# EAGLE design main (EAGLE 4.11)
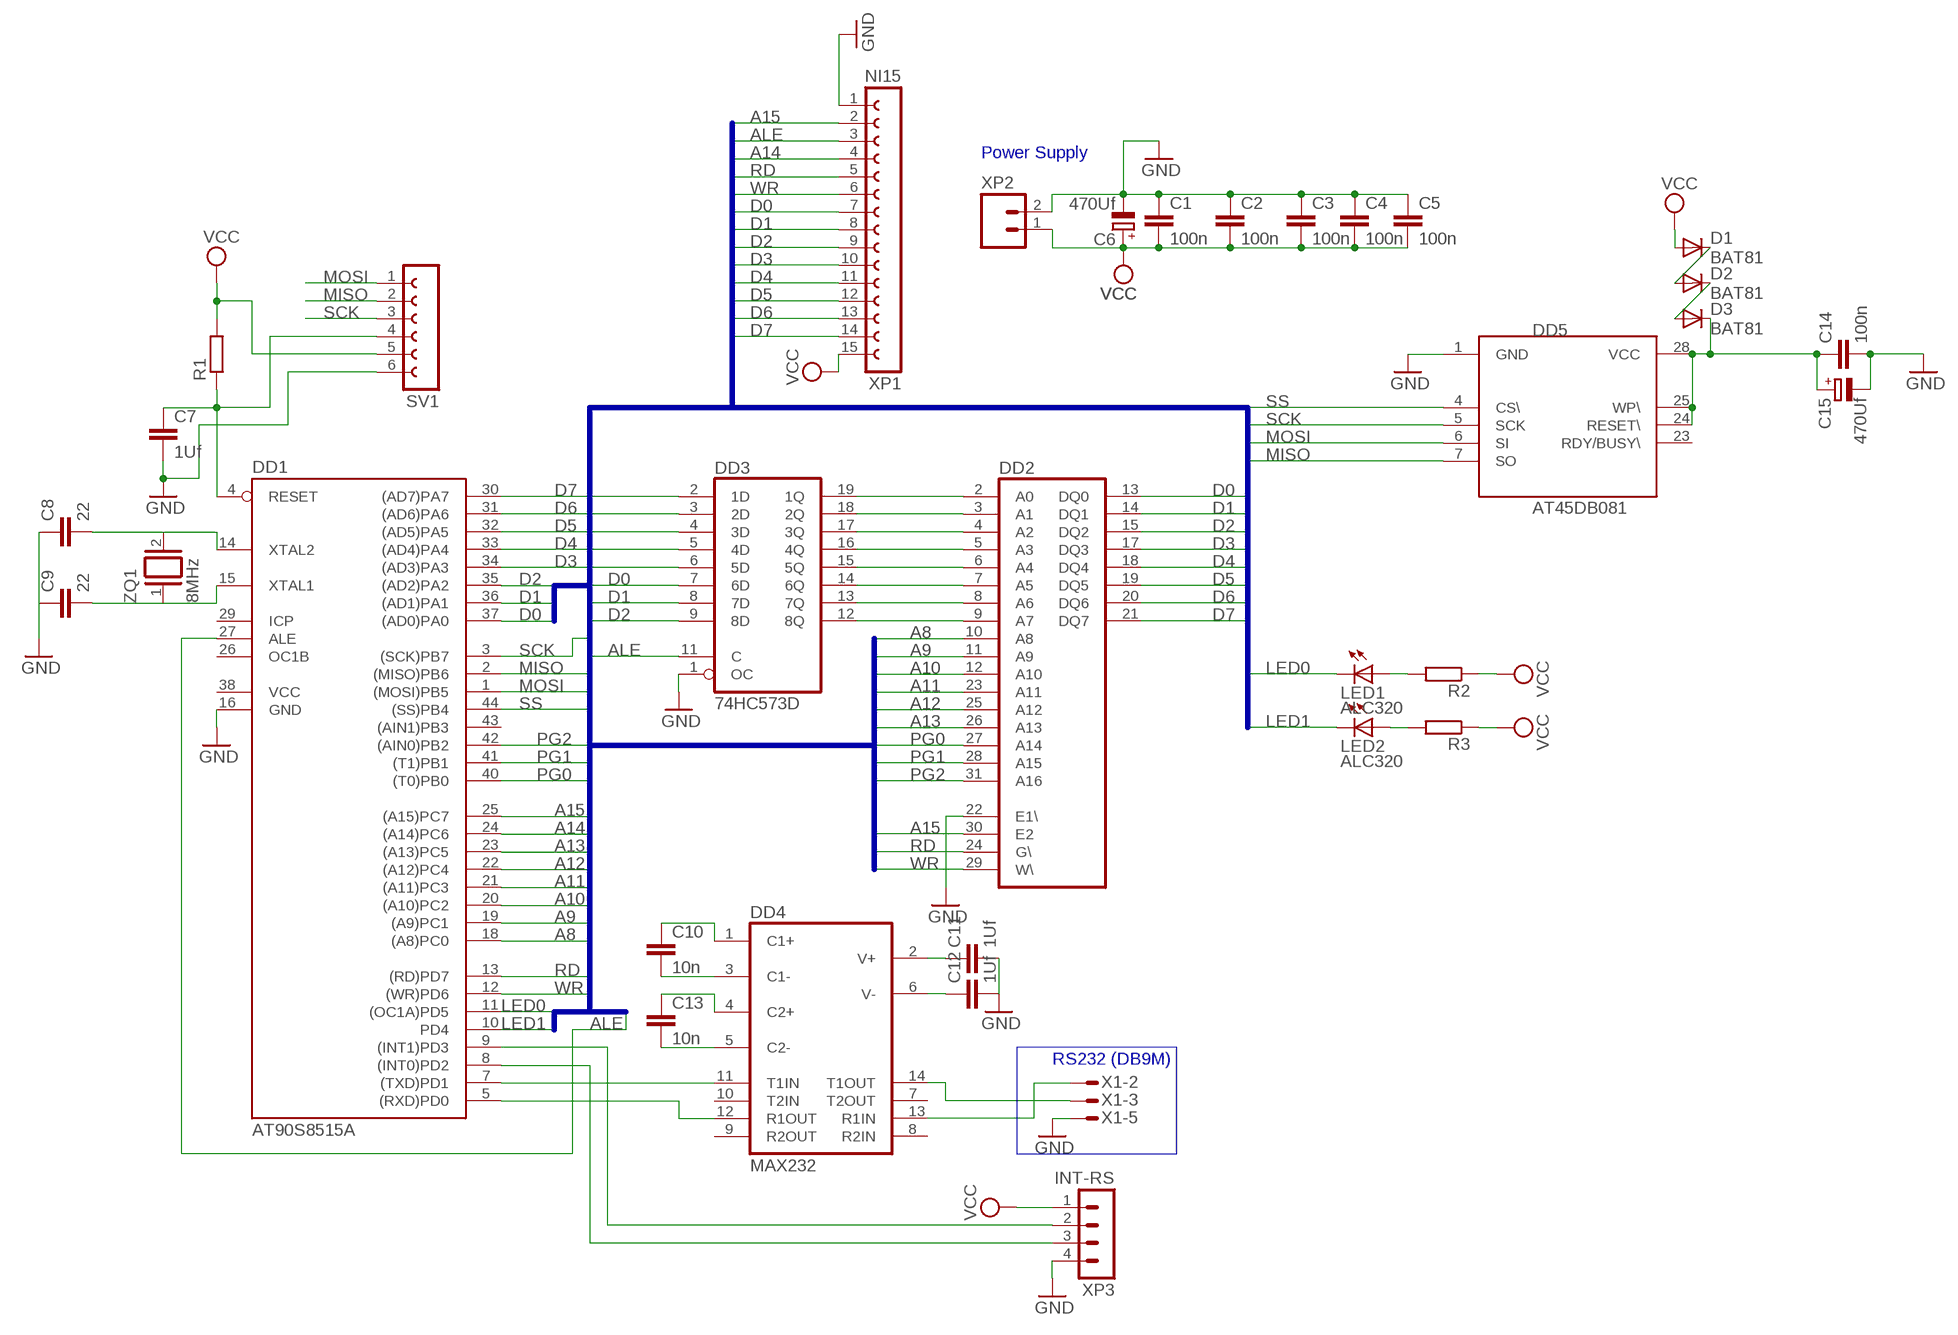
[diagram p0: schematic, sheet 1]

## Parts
C1  100n  C-EUC0805K  [C0805K]
C2  100n  C-EUC0805K  [C0805K]
C3  100n  C-EUC0805K  [C0805K]
C4  100n  C-EUC0805K  [C0805K]
C5  100n  C-EUC0805K  [C0805K]
C6  470Uf  CPOL-EUE2.5-6  [E2,5-6]
C7  1Uf  C-EUC0805K  [C0805K]
C8  22  C-EUC0805K  [C0805K]
C9  22  C-EUC0805K  [C0805K]
C10  10n  C-EUC0805K  [C0805K]
C11  1Uf  C-EUC0805K  [C0805K]
C12  1Uf  C-EUC0805K  [C0805K]
C13  10n  C-EUC0805K  [C0805K]
C14  100n  C-EUC0805K  [C0805K]
C15  470Uf  CPOL-EUE2.5-6  [E2,5-6]
D1  BAT81  [DO34-7]
D2  BAT81  [DO34-7]
D3  BAT81  [DO34-7]
DD1  AT90S8515A  [TQFP44]
DD2  MCM6226A  [SOJ32/4]
DD3  74HC573D  [SO20W]
DD4  MAX232  [DIL16]
DD5  AT45DB081  [AT45DB081-SOIC28]
LED1  ALC320  LED3MM  [LED3MM]
LED2  ALC320  LED3MM  [LED3MM]
R1  R-EU_R0805  [R0805]
R2  R-EU_R0805  [R0805]
R3  R-EU_R0805  [R0805]
SV1  FE06-1  [FE06]
X1  M09HPS  [M09HP]
XP1  NI15  FE15-1  [FE15]
XP2  M02  [02P]
XP3  INT-RS  MA04-1  [MA04-1]
ZQ1  8MHz  XTAL/S  [QS]

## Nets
A8: DD1.18((A8)PC0) DD2.10(A8)
A9: DD1.19((A9)PC1) DD2.11(A9)
A10: DD1.20((A10)PC2) DD2.12(A10)
A11: DD1.21((A11)PC3) DD2.23(A11)
A12: DD1.22((A12)PC4) DD2.25(A12)
A13: DD1.23((A13)PC5) DD2.26(A13)
A14: DD1.24((A14)PC6) XP1.4
A15: DD1.25((A15)PC7) DD2.30(E2) XP1.2
ALE: DD1.27(ALE) DD3.11(C) XP1.3
D0: DD1.37((AD0)PA0) DD2.13(DQ0) DD3.7(6D) XP1.7
D1: DD1.36((AD1)PA1) DD2.14(DQ1) DD3.8(7D) XP1.8
D2: DD1.35((AD2)PA2) DD2.15(DQ2) DD3.9(8D) XP1.9
D3: DD1.34((AD3)PA3) DD2.17(DQ3) DD3.6(5D) XP1.10
D4: DD1.33((AD4)PA4) DD2.18(DQ4) DD3.5(4D) XP1.11
D5: DD1.32((AD5)PA5) DD2.19(DQ5) DD3.4(3D) XP1.12
D6: DD1.31((AD6)PA6) DD2.20(DQ6) DD3.3(2D) XP1.13
D7: DD1.30((AD7)PA7) DD2.21(DQ7) DD3.2(1D) XP1.14
GND: C1.1 C2.1 C3.1 C4.1 C5.1 C6.- C7.2 C8.1 C9.1 C11.2 C12.2 C14.2 C15.- DD1.16(GND) DD2.22(E1\) DD3.1(OC) DD5.1(GND) SV1.6 X1.5 XP1.1 XP2.2 XP3.4
LED0: DD1.11((OC1A)PD5) LED1.K(C)
LED1: DD1.10(PD4) LED2.K(C)
MISO: DD1.2((MISO)PB6) DD5.7(SO) SV1.2
MOSI: DD1.1((MOSI)PB5) DD5.6(SI) SV1.1
N$1: C8.2 DD1.14(XTAL2) ZQ1.2
N$2: C9.2 DD1.15(XTAL1) ZQ1.1
N$3: DD2.2(A0) DD3.19(1Q)
N$4: DD2.3(A1) DD3.18(2Q)
N$5: DD2.4(A2) DD3.17(3Q)
N$6: DD2.5(A3) DD3.16(4Q)
N$7: DD2.6(A4) DD3.15(5Q)
N$8: DD2.7(A5) DD3.14(6Q)
N$9: DD2.8(A6) DD3.13(7Q)
N$10: DD2.9(A7) DD3.12(8Q)
N$11: DD1.8((INT0)PD2) XP3.3
N$12: C7.1 DD1.4(RESET) R1.1 SV1.4
N$13: C12.1 DD4.6(V-)
N$14: C11.1 DD4.2(V+)
N$15: C10.1 DD4.1(C1+)
N$16: C10.2 DD4.3(C1-)
N$17: C13.2 DD4.5(C2-)
N$18: C13.1 DD4.4(C2+)
N$19: DD1.7((TXD)PD1) DD4.11(T1IN)
N$20: DD1.5((RXD)PD0) DD4.12(R1OUT)
N$21: DD4.14(T1OUT) X1.3
N$22: DD4.13(R1IN) X1.2
N$23: DD1.9((INT1)PD3) XP3.2
N$24: LED2.A R3.2
N$25: LED1.A R2.2
N$26: C14.1 C15.+ D3.C DD5.24(RESET\) DD5.25(WP\) DD5.28(VCC)
N$27: D1.C D2.A
N$28: D2.C D3.A
PG0: DD1.40((T0)PB0) DD2.27(A14)
PG1: DD1.41((T1)PB1) DD2.28(A15)
PG2: DD1.42((AIN0)PB2) DD2.31(A16)
RD: DD1.13((RD)PD7) DD2.24(G\) XP1.5
SCK: DD1.3((SCK)PB7) DD5.5(SCK) SV1.3
SS: DD1.44((SS)PB4) DD5.4(CS\)
VCC: C1.2 C2.2 C3.2 C4.2 C5.2 C6.+ D1.A R1.2 R2.1 R3.1 SV1.5 XP1.15 XP2.1 XP3.1
WR: DD1.12((WR)PD6) DD2.29(W\) XP1.6
Unconnected: DD1.6(NC1) DD1.17(NC2) DD1.26(OC1B) DD1.28(NC3) DD1.29(ICP) DD1.39(NC4) DD1.43((AIN1)PB3) DD4.7(T2OUT) DD4.8(R2IN) DD4.9(R2OUT) DD4.10(T2IN) DD5.23(RDY/BUSY\) X1.1 X1.4 X1.6 X1.7 X1.8 X1.9

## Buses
B$1
B$2

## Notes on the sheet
- Power Supply
- RS232 (DB9M)

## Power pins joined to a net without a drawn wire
GND: DD2.16(GND) DD3.10(GND) DD4.15(GND)
VCC: DD1.38(VCC) DD2.32(VCC) DD3.20(VCC) DD4.16(VCC)

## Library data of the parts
C1-C5 C7-C14 = rcl:C-EU: CAPACITOR, European symbol
C6 C15 = rcl:CPOL-EU: POLARIZED CAPACITOR, European symbol
D1-D3 = diode:BAT81: DIODE
DD1 = atmel:AT90S8515: MICROCONTROLLER 8 Kbytes FLASH 512 bytes SRAM 512 bytes EEPROM UART
DD2 = memory-sram:MCM6226A: MEMORY
DD3 = 74xx-eu:74*573: 8-bit D latch BUS DRIVER
DD4 = maxim:MAX232: RS232 TRANSEIVER
DD5 = flash:AT45DB081: Package: SOIC32, 32-pin SOIC package, 1,27mm between center of pins
LED1 LED2 = led:LED: LED
R1-R3 = rcl:R-EU_: RESISTOR, European symbol
SV1 = con-lsta:FE06-1: FEMALE HEADER
X1 = con-subd:M09?S: SUB-D
XP1 = con-lsta:FE15-1: FEMALE HEADER
XP2 = con-amp-quick:M02: AMP QUICK CONNECTOR
XP3 = con-lstb:MA04-1: PIN HEADER
ZQ1 = special:XTAL/S: CRYSTAL

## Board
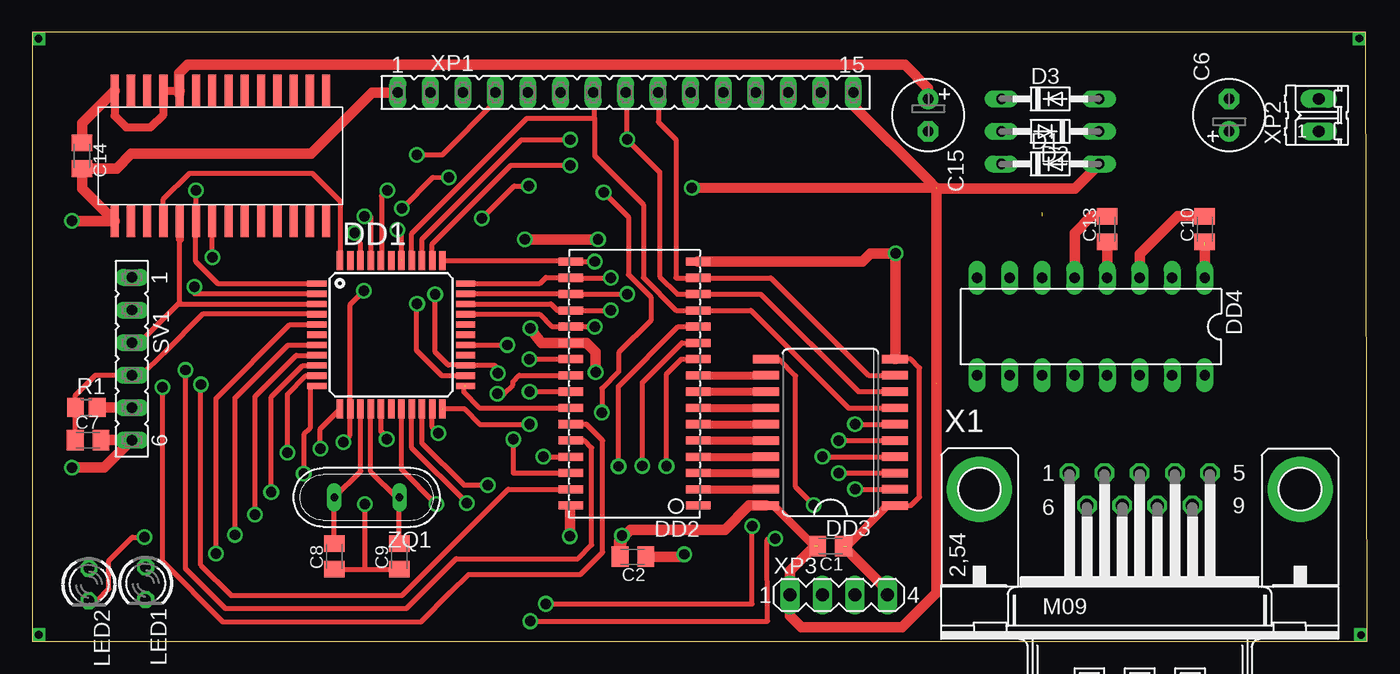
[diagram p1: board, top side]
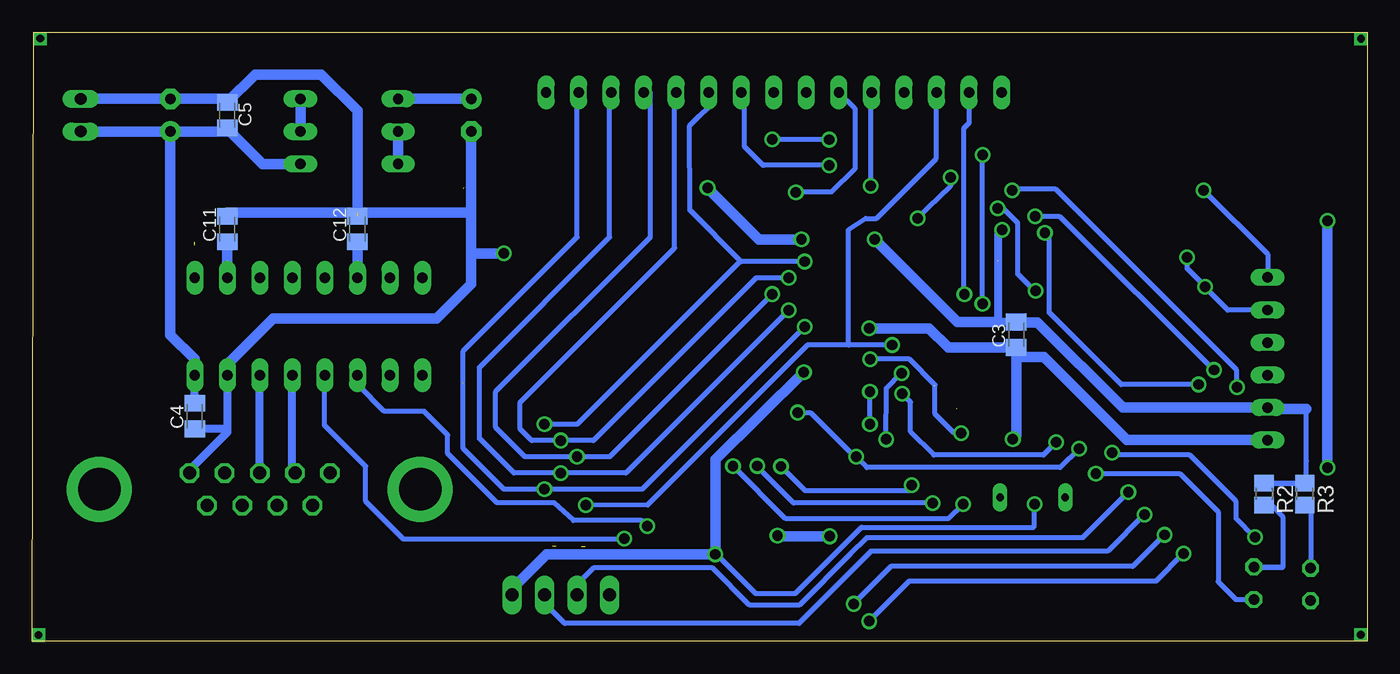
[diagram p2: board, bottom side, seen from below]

Size 104.21 x 47.58 mm. Coordinates in mm from the lower left corner, seen from the top.
Outline: 0,0 104.21,0 104.11,47.58 0,47.58 0,0
Copper layers (1*16): Top 0.035mm / dielectric 1.5mm / Bottom 0.035mm
Design rules "default": minimum track width 10mil, minimum drill 24mil, track to track 8mil, track to pad 8mil, pad to pad 8mil, via to via 8mil, smd to smd 8mil, copper to edge 40mil, drill to drill 8mil, minimum pad ring 10mil, minimum via ring 8mil, stop-mask expansion 4mil, vias tented up to drill 0mil, thermal gap 10mil

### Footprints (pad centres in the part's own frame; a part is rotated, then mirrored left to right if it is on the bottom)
C0805K = smd 1.3 x 1.6: 1 -1,0; 2 1,0
E2,5-6 = drill 0.813 pad 1.6 round: + -1.27,0 | drill 0.813 pad 1.6 octagon: - 1.27,0
DO34-7 = drill 0.813 long: A 3.81,0; C -3.81,0
TQFP44 = smd 1.5 x 0.5: 1 -5.8,4; 2 -5.8,3.2; 3 -5.8,2.4; 4 -5.8,1.6; 5 -5.8,0.8; 6 -5.8,0; 7 -5.8,-0.8; 8 -5.8,-1.6; 9 -5.8,-2.4; 10 -5.8,-3.2; 11 -5.8,-4; 23 5.8,-4; 24 5.8,-3.2; 25 5.8,-2.4; 26 5.8,-1.6; 27 5.8,-0.8; 28 5.8,0; 29 5.8,0.8; 30 5.8,1.6; 31 5.8,2.4; 32 5.8,3.2; 33 5.8,4 | smd 0.5 x 1.5: 12 -4,-5.8; 13 -3.2,-5.8; 14 -2.4,-5.8; 15 -1.6,-5.8; 16 -0.8,-5.8; 17 0,-5.8; 18 0.8,-5.8; 19 1.6,-5.8; 20 2.4,-5.8; 21 3.2,-5.8; 22 4,-5.8; 34 4,5.8; 35 3.2,5.8; 36 2.4,5.8; 37 1.6,5.8; 38 0.8,5.8; 39 0,5.8; 40 -0.8,5.8; 41 -1.6,5.8; 42 -2.4,5.8; 43 -3.2,5.8; 44 -4,5.8
SOJ32/4 = smd 0.635 x 1.905: 1 -8.89,-4.902; 2 -7.62,-4.902; 3 -6.35,-4.902; 4 -5.08,-4.902; 5 -3.81,-4.902; 6 -2.54,-4.902; 7 -1.27,-4.902; 8 0,-4.902; 9 1.27,-4.902; 10 2.54,-4.902; 11 3.81,-4.902; 12 5.08,-4.902; 13 6.35,-4.902; 14 7.62,-4.902; 15 8.89,-4.902; 16 10.16,-4.902; 17 10.16,5.029; 18 8.89,5.029; 19 7.62,5.029; 20 6.35,5.029; 21 5.08,5.029; 22 3.81,5.029; 23 2.54,5.029; 24 1.27,5.029; 25 0,5.029; 26 -1.27,5.029; 27 -2.54,5.029; 28 -3.81,5.029; 29 -5.08,5.029; 30 -6.35,5.029; 31 -7.62,5.029; 32 -8.89,5.029
SO20W = smd 0.66 x 2.032: 1 -5.715,-5.029; 2 -4.445,-5.029; 3 -3.175,-5.029; 4 -1.905,-5.029; 5 -0.635,-5.029; 6 0.635,-5.029; 7 1.905,-5.029; 8 3.175,-5.029; 9 4.445,-5.029; 10 5.715,-5.029; 11 5.715,5.029; 12 4.445,5.029; 13 3.175,5.029; 14 1.905,5.029; 15 0.635,5.029; 16 -0.635,5.029; 17 -1.905,5.029; 18 -3.175,5.029; 19 -4.445,5.029; 20 -5.715,5.029
DIL16 = drill 0.813 long: 1 -8.89,-3.81; 2 -6.35,-3.81; 3 -3.81,-3.81; 4 -1.27,-3.81; 5 1.27,-3.81; 6 3.81,-3.81; 7 6.35,-3.81; 8 8.89,-3.81; 9 8.89,3.81; 10 6.35,3.81; 11 3.81,3.81; 12 1.27,3.81; 13 -1.27,3.81; 14 -3.81,3.81; 15 -6.35,3.81; 16 -8.89,3.81
AT45DB081-SOIC28 = smd 2.54 x 0.635: 1 -1.27,-1.27; 2 -1.27,-2.54; 3 -1.27,-3.81; 4 -1.27,-5.08; 5 -1.27,-6.35; 6 -1.27,-7.62; 7 -1.27,-8.89; 8 -1.27,-10.16; 9 -1.27,-11.43; 10 -1.27,-12.7; 11 -1.27,-13.97; 12 -1.27,-15.24; 13 -1.27,-16.51; 14 -1.27,-17.78; 15 8.89,-17.78; 16 8.89,-16.51; 17 8.89,-15.24; 18 8.89,-13.97; 19 8.89,-12.7; 20 8.89,-11.43; 21 8.89,-10.16; 22 8.89,-8.89; 23 8.89,-7.62; 24 8.89,-6.35; 25 8.89,-5.08; 26 8.89,-3.81; 27 8.89,-2.54; 28 8.89,-1.27
LED3MM = drill 0.813 octagon: A -1.27,0; K 1.27,0
R0805 = smd 1.3 x 1.5: 1 -0.85,0; 2 0.85,0
FE06 = drill 0.813 long: 1 -6.35,0; 2 -3.81,0; 3 -1.27,0; 4 1.27,0; 5 3.81,0; 6 6.35,0
M09HP = drill 1.016 octagon: 1 -5.486,1.27; 2 -2.743,1.27; 3 0,1.27; 4 2.743,1.27; 5 5.486,1.27; 6 -4.115,-1.27; 7 -1.372,-1.27; 8 1.372,-1.27; 9 4.115,-1.27 | drill 3.302 pad 5.08 round: G1 -12.522,0; G2 12.522,0
FE15 = drill 0.813 long: 1 -17.78,0; 2 -15.24,0; 3 -12.7,0; 4 -10.16,0; 5 -7.62,0; 6 -5.08,0; 7 -2.54,0; 8 0,0; 9 2.54,0; 10 5.08,0; 11 7.62,0; 12 10.16,0; 13 12.7,0; 14 15.24,0; 15 17.78,0
02P = drill 0.914 long: 1 -1.27,0; 2 1.27,0
MA04-1 = drill 1.016 long: 1 -3.81,0; 2 -1.27,0; 3 1.27,0; 4 3.81,0
QS = drill 0.61 long: 1 -2.54,0; 2 2.54,0

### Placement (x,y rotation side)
C1  62.33,7.43 180 top
C2  46.89,6.6 180 top
C3  27.4,23.94 90 bottom
C4  91.54,17.59 90 bottom
C5  89,41.08 270 bottom
C6  93.44,41.08 90 top
C7  4.37,15.71 0 top
C8  23.59,6.64 90 top
C9  28.67,6.64 90 top
C10  91.54,32.19 90 top
C11  89,32.19 90 bottom
C12  78.84,32.19 90 bottom
C13  83.92,32.19 90 top
C14  3.91,37.91 270 top
C15  69.95,41.08 270 top
D1  79.47,37.27 0 top
D2  79.47,39.81 180 top
D3  79.47,42.35 0 top
DD1  28.04,23.94 0 top
DD2  47.09,19.49 90 top
DD3  62.33,16.32 90 top
DD4  82.65,24.57 180 top
DD5  5.18,34.1 90 top
LED1  8.86,4.53 270 top
LED2  4.44,4.44 270 top
R1  4.23,18.27 0 top
R2  8.07,11.49 270 bottom
R3  4.9,11.49 270 bottom
SV1  7.78,22.06 270 top
X1  86.46,11.87 0 top
XP1  46.33,42.85 0 top
XP2  100.43,41.08 90 top
XP3  62.96,3.62 0 top
ZQ1  26.13,11.24 180 top

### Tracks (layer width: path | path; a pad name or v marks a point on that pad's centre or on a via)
A8  (via drill 0.81)
  Top 0.406: DD2.10 50.67,22.03 49.52,20.88 v49.52,13.68 | DD1.18 28.84,13.42 v31.55,10.71
  Bottom 0.406: v49.52,13.68 45.41,9.57 32.72,9.57 v31.55,10.71
A9  (via drill 0.81)
  Top 0.406: DD2.11 50.71,23.3 47.64,20.23 v47.64,13.7 | DD1.19 29.62,18.14 29.62,15.09 v33.94,10.79
  Bottom 0.406: v47.64,13.7 47.68,13.7 44.78,10.8 33.95,10.8 v33.94,10.79
A10  (via drill 0.81)
  Top 0.406: DD2.12 50.43,24.57 45.77,19.92 v45.77,13.66 | DD1.20 30.44,18.25 | DD1.20 | v35.57,12.2 33.7,12.2 30.44,15.47 DD1.20
  Bottom 0.406: v45.77,13.66 43.87,11.76 35.57,11.76 v35.57,12.2
A11  (via drill 0.81)
  Top 0.406: v38.8,22.03 DD2.23 | v38.8,22.03 | DD1.21 31.24,18.18 | DD1.21 | v31.72,16.25 31.24,16.73 DD1.21
  Bottom 0.406: v38.8,22.03 35.75,22.03 33.74,20.02 33.74,17.76 32.23,16.25 v31.72,16.25
A12  (via drill 0.81)  (1 unrouted)
  Top 0.406: v38.83,19.49 DD2.25 | v38.83,16.95 34.92,16.95 33.75,18.13 33.75,18.17 32.03,18.18
  Bottom 0.406: v38.83,16.95 v38.83,19.49
A13  (1 unrouted)
  Top 0.406: DD2.26 34.95,18.22 33.72,19.46 33.72,20.01 33.75,19.94
A14  (via drill 0.81)
  Top 0.406: XP1.4 36.16,42.91 | XP1.4 | v30.05,37.99 32.04,38 36.16,42.12 XP1.4 | DD1.24 33.82,20.74 33.82,20.73 | DD1.24 | DD1.24 | DD1.24 | 33.92,20.74 | DD1.24 33.92,20.74 | 33.92,20.74 | v30.05,26.37 30.03,26.37 30.03,22.69 31.98,20.74 33.92,20.74
  Bottom 0.406: v30.05,26.37 30.06,26.39 v30.05,37.99
A15  (via drill 0.81)
  Top 0.406: DD2.30 38.8,13.14 37.57,13.14 v37.57,15.77 | v36.36,20.94 36.36,21.26 36.08,21.54 33.86,21.54 | 33.86,21.54 DD1.25 | 33.86,21.54 33.86,21.57 32.47,21.57 31.46,22.58 v31.46,27.09
  Bottom 0.406: v37.57,15.77 37.54,19.76 v36.36,20.94 | v31.46,27.09 31.48,27.09 31.48,40.08 31.07,40.49 31.07,42.86 | 31.07,42.89 31.07,42.86 | 31.07,42.86 XP1.2
ALE  (via drill 0.81)
  Top 0.406: DD1.27 v37.09,23.14 | v61.02,10.63 59.59,12.06 59.59,20.74 58.3,22.03 DD3.11
  Bottom 0.406: v61.02,10.63 56.18,10.65 43.74,23.09 43.74,23.14 v37.09,23.14 40.5,23.14 40.5,32.14 39.16,33.03 38.34,33.02 33.64,37.71 33.64,42.86 | 33.63,42.14 XP1.3 33.64,42.86 | 33.64,42.86 33.64,42.87
D0
  Top 0.406: 43.91,42.86 43.91,42.91 | 43.91,42.86 XP1.7 | 43.91,40.84 43.91,37.91 47.72,34.1 47.72,28.4 50.27,25.84 DD2.13 56.11,25.84 63.73,18.22 DD3.7 | 43.91,40.84 43.91,42.86 | 29.67,29.74 DD1.37 29.63,31.84 38.63,40.84 43.91,40.84
D1  (via drill 0.81)
  Top 0.406: 46.45,42.86 46.45,42.91 | 46.45,42.86 XP1.8 | 46.45,42.86 v46.45,39.18 48.99,36.64 48.99,28.5 50.37,27.11 DD2.14 56.87,27.11 64.49,19.49 DD3.8 | DD1.36 30.43,31.4 38.2,39.17 v42.02,39.17
  Bottom 0.406: v46.45,39.18 v42.02,39.18 v42.02,39.17
D2  (via drill 0.81)
  Top 0.406: 50.26,28.38 DD2.15 | 50.26,28.38 50.26,39.18 48.88,40.55 48.88,42.86 XP1.9 | DD3.9 65.28,20.76 57.66,28.38 50.26,28.38 | DD1.35 31.23,29.68 | DD1.35 | v42.01,37.17 37.38,37.17 31.23,31.03 DD1.35
  Bottom 0.406: v42.01,37.17 42.01,37.18 47.13,37.18 47.18,37.18 | XP1.9 48.61,42.86 48.61,38.61 47.18,37.18 | 47.18,37.18
D3  (via drill 0.81)
  Top 0.406: 42.19,29.74 42.19,29.65 DD2.17 v43.91,29.65 | DD1.34 42.19,29.74 | 42.19,29.74 | v64.23,16.95 DD3.6
  Bottom 0.406: v64.23,16.95 61.69,16.95 49.07,29.58 48.88,29.65 | v43.91,29.65 48.88,29.65 | 48.88,29.65 48.88,29.61 | 48.88,29.65 52.89,33.66 52.91,40.25 52.12,41.03 51.43,41.72 51.43,43.19 XP1.10
D4  (via drill 0.81)
  Top 0.406: DD1.33 39.64,27.94 40.11,28.42 42.04,28.42 42.04,28.38 DD2.18 v45.18,28.38 | v62.96,15.68 DD3.5
  Bottom 0.406: v45.18,28.38 47.72,28.38 60.42,15.68 v62.96,15.68 65.24,15.68 66.14,16.58 66.14,18.66 54.07,30.72 54.07,42.86 XP1.11
D5  (via drill 0.81)
  Top 0.406: 42.14,27.14 42.14,27.11 DD2.19 v46.45,27.11 | DD1.32 42.14,27.14 | 42.14,27.14 42.14,27.16 | v61.69,14.41 DD3.4
  Bottom 0.406: v46.45,27.11 59.15,14.41 v61.69,14.41 65.75,14.41 68.04,16.7 68.04,19.49 55.98,31.56 55.98,42.86 XP1.12
D6  (via drill 0.81)
  Top 0.406: DD1.31 40.5,26.34 41.01,25.84 41.99,25.84 | 41.99,25.84 41.99,25.89 | 41.99,25.84 DD2.20 v45.18,25.84 | v62.96,13.14 DD3.3
  Bottom 0.406: v45.18,25.84 57.88,13.14 v62.96,13.14 66.62,13.14 69.31,15.84 69.31,21.4 59.15,31.56 59.15,42.86 XP1.13
D7  (via drill 0.81)
  Top 0.406: DD1.30 39.61,25.54 40.56,24.58 42.04,24.58 | 42.04,24.58 42.04,24.57 DD2.21 v43.91,24.57 | 42.04,24.58 42.04,24.61 | v64.23,11.87 DD3.2
  Bottom 0.406: v43.91,24.57 56.61,11.87 v64.23,11.87 67.41,11.87 70.58,15.05 70.58,22.67 61.69,31.56 61.69,42.86 XP1.14
GND  (via drill 0.81)  (3 unrouted)
  Top 0.406: 67.43,22.03 DD3.10 | DD3.1 68.59,10.6 69.26,11.28 69.26,21.36 68.59,22.03 67.43,22.03 | 67.43,22.03 67.43,22.01 | DD1.16 27.24,16.38 27.68,15.95 v27.68,15.79 | 7.72,15.71 7.72,15.69 | SV1.6 7.72,15.71 | 7.72,15.71 | v25.98,10.71 25.98,5.64 | C8.1 25.98,5.64 | 25.98,5.64 | 25.98,5.64 C9.1 | 25.98,5.64 25.98,5.66
  Top 0.61: DD3.1 66.77,10.6 63.6,7.43
  Top 0.813: XP3.4 66.77,3.98 C1.1 | C2.1 50.7,6.6 v50.9,6.79 | DD3.10 67.41,22.03 v67.41,30.29 67.5,30.29 | v43.98,21.01 43.98,22.58 43.28,23.29 42.07,23.29 42.07,23.3 DD2.22 39.76,23.3 v38.87,24.45 | DD2.16 64.8,29.65 65.43,30.28 67.5,30.28 67.5,30.29 | 67.5,30.29 67.5,30.34 | 7.72,15.71 C7.2 | v3.12,32.84 3.12,32.83 DD5.1 3.91,35.37 C14.2 4.06,36.91 | SV1.6 5.64,13.57 v3.12,13.57 | XP1.1 26.55,42.86 21.78,38.08 7.75,38.08 6.59,36.92 4.06,36.92 4.06,36.91 | 4.06,36.91 4.06,36.85
  Bottom 0.406: 27.4,22.97 C3.1 | v25.98,10.71 26.03,10.71 26.04,8.9 | 26.04,8.9 39.48,8.9 44.65,3.73 47.76,3.73 50.81,6.79 v50.9,6.79
  Bottom 0.61: X1.5 92.17,13.14 89,16.32 89,16.95 | DD4.15 89,16.95 | C4.1 89,16.59 89,16.95
  Bottom 0.813: XP3.4 66.77,4.1 64.08,6.79 v50.9,6.79 50.9,14.19 v43.98,21.01 | XP2.2 C6.- 89,42.35 C5.1 | C11.2 89,33.46 78.84,33.46 | 78.84,33.46 78.84,41.42 81.68,44.26 86.82,44.26 C5.1 | 69.95,33.46 C15.- | 69.95,33.46 78.84,33.46 | 69.95,30.29 69.95,33.46 | 69.95,30.29 69.95,27.9 72.64,25.21 85.4,25.21 89,21.62 DD4.15 | v67.41,30.29 69.95,30.29 | v27.68,15.79 27.4,16.08 27.4,22.21 | 27.4,22.21 C3.1 | 27.4,22.21 25.27,22.21 18.77,15.71 SV1.6 | C5.1 89,42.08 | v38.87,24.45 34.22,24.45 32.7,22.94 27.55,22.94 | 27.55,22.94 27.55,22.88 | C3.1 27.55,22.94 | v3.12,13.57 v3.12,32.84
LED0  (via drill 0.81)
  Top 0.406: DD1.11 21.7,19.94 21.7,16.63 21.2,16.14 v21.2,13.1
  Bottom 0.406: v21.2,13.1 14.65,13.1 11.65,10.11 11.65,4.66 10.27,3.28 LED1.K | LED1.K | LED1.K 8.86,3.34
LED1  (via drill 0.81)
  Top 0.406: LED2.K 5.07,3.17 5.99,4.09 5.99,6.3 7.82,8.13 v8.78,8.13 | DD1.10 22.16,20.74 22.16,20.72 21.37,20.72 19.94,19.29 v19.94,14.72
  Bottom 0.406: v8.78,8.13 10.25,9.6 10.25,10.92 13.87,14.54 19.94,14.54 v19.94,14.72
MISO  (via drill 0.81)
  Top 0.406: DD1.2 12.66,27.14 v12.66,27.69 | DD5.7 v14.07,29.98
  Bottom 0.406: v14.07,29.98 14.07,29.1 v12.66,27.69 12.72,27.69 | 12.72,27.69 12.72,27.76 | SV1.2 10.9,25.87 12.72,27.69
MOSI  (via drill 0.81)
  Top 0.406: 12.78,32.83 12.78,32.9 | 12.78,32.83 DD5.6 v12.79,35.23 | DD1.1 14.48,27.94 12.78,29.64 12.78,32.83
  Bottom 0.406: 7.79,28.34 SV1.1 | SV1.1 | v12.79,35.23 7.79,30.23 SV1.1
N$1
  Top 0.406: DD1.14 25.65,18.14 25.65,13.27 25.63,13.27 ZQ1.2 C8.2
N$2
  Top 0.406: 28.43,11.24 26.44,13.23 DD1.15 | DD1.15 | ZQ1.1 28.65,11.24 28.65,7.64 C9.2
  Top 0.61: 28.43,11.24 ZQ1.1
N$3
  Top 0.61: DD2.2 DD3.19
N$4
  Top 0.61: DD2.3 DD3.18
N$5
  Top 0.61: DD2.4 DD3.17
N$6
  Top 0.61: DD2.5 DD3.16
N$7
  Top 0.61: DD2.6 DD3.15
N$8
  Top 0.61: DD2.7 DD3.14
N$9
  Top 0.61: DD2.8 DD3.13
N$10
  Top 0.61: DD2.9 DD3.12
N$11  (via drill 0.81)
  Top 0.406: v17.4,9.9 17.4,19.11 20.63,22.34 DD1.8
  Bottom 0.406: v17.4,9.9 v17.41,9.9 20.27,7.04 38.77,7.04 44.37,1.41 62.65,1.41 64.27,3 64.28,3.62 XP3.3
N$12
  Top 0.406: 3.35,18.27 3.35,18.3 | 3.35,18.27 R1.1 | C7.1 3.35,15.71 3.35,18.27 | R1.1 3.38,18.24 | R1.1 3.38,19.21 4.96,20.79 SV1.4 7.74,20.79 | 7.74,20.61 7.74,20.79 | DD1.4 13.3,25.54 10.25,22.49 8.56,20.8 7.74,20.8 7.74,20.79
N$13
  Bottom 0.813: DD4.6 C12.1
N$14
  Bottom 0.813: DD4.2 C11.1
N$15  (1 unrouted)
  Top 0.813: DD4.1 91.54,30.92
N$16
  Top 0.813: C10.2 89.42,33.19 86.46,30.23 DD4.3
N$17
  Top 0.813: C13.2 82.7,33.19 81.38,31.87 DD4.5
N$18
  Top 0.813: DD4.4 C13.1
N$19  (via drill 0.81)
  Top 0.406: 56.19,9 v56.21,9 56.19,9 | v15.85,8.31 15.85,19.02 19.97,23.14 DD1.7 | 56.2,2.9 56.2,2.89 | v40.1,2.93 56.13,2.93 56.2,2.9 | 56.19,9 56.19,9.02 | 56.2,2.9 56.19,2.91 56.19,9
  Bottom 0.406: v56.21,9 56.65,9.44 61.97,9.43 63.49,10.82 67.94,10.82 71.78,14.66 71.78,16.11 73.63,17.96 73.64,17.96 73.64,17.95 76.74,17.95 78.79,20 78.79,20.76 DD4.11 | v15.85,8.31 18.32,5.84 37.19,5.84 v40.1,2.93
N$20  (via drill 0.81)
  Top 0.406: v58.01,8.03 57.42,7.98 57.38,7.92 | v14.35,6.86 14.35,18.97 20.12,24.74 DD1.5 | v38.9,1.57 57.39,1.57 | 57.38,7.92 57.98,7.98 | 57.39,1.57 57.4,1.57 | 57.39,1.57 57.38,7.92
  Bottom 0.406: DD4.12 81.4,20.76 81.4,16.87 78.19,13.66 78.19,10.93 75.23,7.97 57.92,7.97 v58.01,8.03 | v14.35,6.86 16.51,4.7 35.77,4.7 v38.9,1.57
N$21
  Bottom 0.61: X1.3 DD4.14
N$22
  Bottom 0.61: X1.2 83.92,13.14 DD4.13
N$23  (via drill 0.81)
  Top 0.406: DD1.9 21.12,21.54 18.66,19.08 v18.66,11.64
  Bottom 0.406: v18.66,11.64 18.69,11.64 22.24,8.1 39.07,8.1 40.38,6.78 44.34,2.82 48.22,2.82 51.12,5.73 60.4,5.73 61.71,4.41 61.71,3.62 | 61.71,3.62 61.71,3.48 | 61.71,3.62 XP3.2
N$24
  Bottom 0.406: 4.42,5.66 4.42,5.71 | 4.42,5.71 LED2.A | R3.2 4.42,10.16 4.42,5.71
N$25
  Bottom 0.406: 8.87,5.74 6.61,5.77 | 6.61,5.77 LED1.A | R2.2 7.52,10.64 6.61,9.73 6.61,5.77
N$26
  Top 0.61: DD5.28 6.45,41.03 7.34,40.13 9.25,40.13 10.26,41.13 DD5.25 DD5.24
  Top 0.813: C14.1 3.91,40.45 DD5.28 | C15.+ 69.94,43.2 68.13,45.02 12.17,45.02 11.49,44.36 11.49,42.99 | 11.49,42.76 11.49,42.99 | 11.49,42.99 DD5.24
  Bottom 0.813: C15.+ D3.C
N$27
  Bottom 0.813: D1.C D2.A
N$28
  Bottom 0.813: D2.C D3.A
N$29  (via drill 0.61)
  other vias: 0.5,47.05
N$30  (via drill 0.61)
  other vias: 103.59,47.07
N$31  (via drill 0.61)
  other vias: 103.72,0.49
N$32  (via drill 0.61)
  other vias: 0.51,0.51
PG0  (via drill 0.81)
  Top 0.406: DD2.27 43.27,16.95 44.54,15.68 44.54,6.96 42.81,5.23 34.07,5.23 32.65,3.81 30.34,1.5 14.91,1.5 10.18,6.24 v10.18,19.84 | 27.27,29.62 27.27,29.74 | 27.27,29.74 DD1.40 | v27.73,35.23 27.27,34.77 27.27,29.74
  Bottom 0.406: v10.18,19.84 10.2,19.84 10.2,21.18 24.32,35.29 27.73,35.29 v27.73,35.23
PG1  (via drill 0.81)
  Top 0.406: DD2.28 43.1,15.68 43.68,15.11 43.68,7.52 42.61,6.46 33.11,6.46 29.2,2.55 15.11,2.55 11.98,5.68 v11.98,21.19 | 26.43,29.7 DD1.41 | DD1.41 | v25.92,33.17 26.43,33.14 DD1.41
  Bottom 0.406: v11.98,21.19 24.01,33.16 v25.92,33.17
PG2  (via drill 0.81)
  Top 0.406: DD2.31 37.16,11.87 28.87,3.59 15.52,3.59 13.17,5.95 v13.17,20.06 | DD1.42 25.63,29.69 | DD1.42 | v25.17,31.9 25.63,31.1 DD1.42
  Bottom 0.406: v13.17,20.06 19.21,20.06 24.83,25.67 24.82,25.67 24.82,31.83 25.25,31.83 25.25,31.9 v25.17,31.9
RD  (via drill 0.81)
  Top 0.406: DD2.24 38.03,20.76 37.53,20.27 37.53,20.03 36.85,19.35 36.3,19.35 v36.3,19.32 | 24.82,18.14 24.82,18.15 | 24.82,18.14 DD1.13 | v24.29,15.56 24.82,16.09 24.82,18.14 | v35.12,33.04 37.64,35.56 v38.76,35.56 | v28.86,33.8 31.29,36.23 v32.54,36.21 | DD1.13 | DD1.13 24.83,26.3 v25.89,27.36
  Bottom 0.406: v36.3,19.32 35.66,18.69 35.66,16.37 33.85,14.55 25.29,14.55 v24.29,15.56 | XP1.5 38.76,42.86 v38.76,35.56 | v32.54,36.21 32.56,35.52 v35.12,33.04 | v28.86,33.8 28.42,33.8 27.29,32.67 27.29,28.67 25.89,27.27 v25.89,27.36
SCK
  Top 0.406: 11.53,31.99 11.5,31.99 11.5,26.46 | DD1.3 11.5,26.34 11.5,26.46 | 11.5,26.46 11.53,26.46 11.53,26.44 8.42,23.33 SV1.3
  Top 0.61: 11.53,31.41 11.53,31.99 DD5.5
SS
  Top 0.406: DD1.44 24.04,34.38 21.87,36.56 12.28,36.56 10.25,34.53 DD5.4 | DD5.4 10.25,32.75 | DD5.4
VCC  (via drill 0.81)  (4 unrouted)
  Top 0.406: 28.82,32.11 28.82,32.16 | v28.52,32.12 28.82,32.11 | 28.82,29.74 28.82,32.11 | DD2.32 42.01,10.6 | DD2.32 42.04,10.6 | 45.95,6.6 C2.2 | 45.95,6.6 45.95,6.55 | 45.9,6.6 45.95,6.6 | 41.99,10.5 DD2.32 | v41.97,8.2 42,8.02 | 7.88,18.25 7.88,18.21 | SV1.5 7.88,18.25 | 7.88,18.25 7.88,18.27
  Top 0.61: DD3.20 57.88,10.6 61.06,7.43 | 64.23,42.91 64.23,42.86 XP1.15
  Top 0.813: 61.06,7.43 59.15,5.52 XP3.1 59.15,1.98 60.05,1.08 67.89,1.08 70.58,3.77 70.58,20.13 | C2.2 45.82,6.6 45.82,7.8 46.71,8.7 54.07,8.7 55.98,10.6 DD3.20 | 70.58,35.37 69.87,36.08 | 69.87,36.08 64.23,41.72 64.23,42.86 | 70.58,20.17 70.58,35.37 | v46.05,8.26 45.9,6.6 | 42,8.02 41.99,10.5 | 7.88,18.27 R1.2 | v38.46,31.38 44.2,31.37 v44.18,31.38 | 69.87,36.08 | v51.51,35.4 70.55,35.42 | D1.A 81.38,35.37 70.58,35.37
  Bottom 0.406: 8.02,12.34 R2.1 4.77,12.35 4.77,14.06 | R3.1 8.02,12.34 | 8.02,12.34 8.02,12.48 | 4.77,14.06 4.77,14.05 | 4.77,14.06 4.77,18.14 | SV1.5 7.85,18.25 7.85,18.14
  Bottom 0.61: C3.2 28.8,24.94 | v28.52,32.12 28.8,32.11 28.8,24.94 | 28.8,24.94 28.82,24.94 | C4.2 DD4.16
  Bottom 0.813: C6.+ XP2.1 | DD4.16 91.54,22.03 93.44,23.94 C6.+ | v46.05,8.26 46.02,8.2 v41.97,8.2 | SV1.5 19.11,18.25 25.76,24.9 27.33,24.9 27.37,24.94 C3.2 | 4.77,18.14 7.85,18.14 | 28.82,24.94 32.02,24.94 v38.46,31.38 | v44.18,31.38 47.49,31.38 v51.51,35.4 | C6.+ 89.02,39.81 89.02,40.08 | 89.02,40.08 89.02,40.1 | 89.02,40.08 C5.2 | 89.02,40.08 86.21,37.27 D1.A
WR  (via drill 0.81)
  Top 0.406: DD1.12 22.5,16.6 v22.5,15.04 | 41.98,14.41 | 41.98,14.41 DD2.29 | v39.91,14.41 41.98,14.41 | v44.61,35.06 46.54,33.13 46.54,28.62 48.3,26.87 48.3,25.07 45.78,22.55 45.78,21.06 44.47,19.76 v44.47,17.87
  Bottom 0.406: v22.5,15.04 23.97,13.57 39.07,13.57 v39.91,14.41 40.02,14.41 | XP1.6 40.02,41.62 40.02,36.89 41.83,35.08 44.61,35.08 v44.61,35.06 | 40.02,14.4 40.02,14.41 | v44.47,17.87 43.47,17.87 40.02,14.41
